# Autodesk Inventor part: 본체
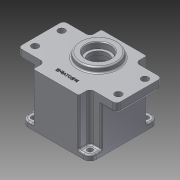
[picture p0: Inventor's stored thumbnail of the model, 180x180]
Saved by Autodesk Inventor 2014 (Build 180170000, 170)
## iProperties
Created: 2015-07
Part Number: 본체
Material: 알루미늄 6061
Document SubType Name: Modeling
Designer: Administrator
Density: 2.71 g/cm^3
Appearance: 알루미늄 - 평지
Mass: 704.944 g
Surface Area: 674.656 cm^2
Volume: 260.127 cm^3
Author: Administrator
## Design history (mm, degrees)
sketch "스케치1"
  geometry: L1 (-45, 45)-(45, 45); L2 (45, 45)-(45, -45); L3 (45, -45)-(-45, -45); L4 (-45, -45)-(-45, 45); L5 (-45, 45)-(45, -45); L6 (45, 45)-(-45, -45); 1 further point
  constraints: 12 end point, 2 midpoint, 2 parallel, 1 horizontal, 1 perpendicular
  dimensions: "d0" = 90 distance of L2.end L3.end; "d1" = 90 distance of L1.end L2.end
extrude "돌출1" new body sketch "스케치1" distance "d2" = 7; taper "d3" = 0 deg
sketch "스케치2"
  geometry: L1 (-30, 45)-(30, 45); L2 (30, 45)-(30, -45); L3 (30, -45)-(-30, -45); L4 (-30, -45)-(-30, 45); L5 (-30, 45)-(30, -45); L6 (30, 45)-(-30, -45); 3 further points
  constraints: 12 end point, 3 midpoint, 2 parallel, 1 coincident, 1 horizontal, 1 perpendicular
  dimensions: "d4" = 60 distance of L1.start L1.end; "d5" = 90 distance of L1.end L2.end
extrude "돌출2" join sketch "스케치2" distance "d6" = 63; taper "d7" = 0 deg
sketch "스케치3"
  geometry: L1 (-65, 30)-(65, 30); L2 (65, 30)-(65, -30); L3 (65, -30)-(-65, -30); L4 (-65, -30)-(-65, 30); L5 (-65, 30)-(65, -30); L6 (65, 30)-(-65, -30); 1 further point
  constraints: 12 end point, 2 midpoint, 2 parallel, 1 horizontal, 1 perpendicular
  dimensions: "d8" = 130 distance of L2.end L3.end; "d9" = 60 distance of L1.end L2.end
extrude "돌출3" join sketch "스케치3" distance "d10" = 12; taper "d11" = 0 deg
sketch "스케치4"
  geometry: L1 (-45, 30)-(45, 30); L2 (45, 30)-(45, -30); L3 (45, -30)-(-45, -30); L4 (-45, -30)-(-45, 30); L5 (-45, 30)-(45, -30); L6 (45, 30)-(-45, -30); 1 further point
  constraints: 12 end point, 2 midpoint, 2 parallel, 1 horizontal, 1 perpendicular
  dimensions: "d12" = 60 distance of L1.end L2.end; "d13" = 90 distance of L2.end L3.end
extrude "돌출4" join sketch "스케치4" distance "d14" = 63; taper "d15" = 0 deg
sketch "스케치5"
  geometry: C1 r 40 at (0, 0); 1 further point
  constraints: 1 centre point, 1 coincident
  dimensions: "d16" = 80 diameter of C1
extrude "돌출5" cut sketch "스케치5" distance "d17" = 9; taper "d18" = 0 deg
sketch "스케치6"
  geometry: C1 r 40 at (0, 0) reference; C2 r 39 at (0, 0)
  constraints: 1 centre point, 1 coincident
  dimensions: "d19" = 78 diameter of C2
extrude "돌출6" cut sketch "스케치6" distance "d20" = 52; taper "d21" = 0 deg
sketch "스케치7"
  geometry: C1 r 39 at (0, 0) reference; C2 r 20.5 at (0, 11); C3 r 14 at (0, -20)
  constraints: 2 centre point, 2 vertical alignment
  dimensions: "d22" = 11 distance of C1.centre C2.centre; "d23" = 20.5 radius of C2; "d24" = 28 diameter of C3; "d25" = 20 distance of C1.centre C3.centre
extrude "돌출7" join sketch "스케치7" distance "d26" = 7; taper "d27" = 0 deg
sketch "스케치8"
  geometry: C1 r 17.5 at (0, 11); A1 r 20.5 centre (0, 11) between (7.402, -8.117) and (-7.402, -8.117) reference; 1 further point
  constraints: 1 centre point, 1 coincident
  dimensions: "d30" = 35 diameter of C1
extrude "돌출8" cut sketch "스케치8" distance "d31" = 10; taper "d32" = 0 deg
sketch "스케치9"
  geometry: C1 r 11 at (0, -20); A1 r 14 centre (0, -20) between (-7.402, -8.117) and (7.402, -8.117) reference; 1 further point
  constraints: 1 centre point, 1 coincident
  dimensions: "d33" = 22 diameter of C1
extrude "돌출9" cut sketch "스케치9" distance "d34" = 7; taper "d35" = 0 deg
sketch "스케치10"
  geometry: C1 r 17.5 at (0, 0) reference; C2 r 12.5 at (0, 0); 1 further point
  constraints: 1 centre point, 1 coincident
  dimensions: "d36" = 25 diameter of C2
extrude "돌출10" cut sketch "스케치10" distance "d37" = 5; taper "d38" = 0 deg
sketch "스케치11"
  geometry: C1 r 11 at (0, 0) reference; C2 r 9.5 at (0, 0); 1 further point
  constraints: 1 centre point, 1 coincident
  dimensions: "d39" = 19 diameter of C2
extrude "돌출11" cut sketch "스케치11" distance "d40" = 1; taper "d41" = 0 deg
sketch "스케치12"
  geometry: C1 r 25 at (0, 11); 1 further point
  constraints: 1 centre point, 1 vertical alignment
  dimensions: "d42" = 50 diameter of C1; "d43" = 11 distance of point (0, 0) C1.centre
extrude "돌출12" join sketch "스케치12" distance "d44" = 7; taper "d45" = 0 deg
sketch "스케치13"
  geometry: C1 r 25 at (0, 0) reference; C2 r 16 at (0, 0); 1 further point
  constraints: 1 centre point, 1 coincident
  dimensions: "d46" = 32 diameter of C2
extrude "돌출13" cut sketch "스케치13" distance "d47" = 8; taper "d48" = 0 deg
sketch "스케치14"
  geometry: L1 (0, 0)-(39, 0); L2 (0, 0)-(24.749, 24.749); L3 (27.411, 21.763)-(30.401, 24.429); L4 (21.763, 27.411)-(24.429, 30.401); A1 r 39 centre (0, 0) between (39, 0) and (30.256, 24.608) reference; A2 r 35 centre (0, 0) between (24.749, 24.749) and (27.411, 21.763); A3 r 4 centre (24.749, 24.749) between (27.411, 21.763) and (21.763, 27.411); 1 further point
  constraints: 10 point on circle, 8 end point, 2 centre point, 2 coincident, 2 tangent, 1 horizontal
  dimensions: "d49" = 70 diameter of A2; "d50" = 45 deg angle of L1 L2; "d51" = 8 diameter of A3
extrude "돌출14" join sketch "스케치14" stored distance "d52" = 8; taper "d53" = 0 deg
sketch "스케치15"
  geometry: A1 r 4 centre (24.749, -24.749) between (27.411, -21.763) and (21.763, -27.411) reference; A2 r 4 centre (-24.749, -24.749) between (-21.763, -27.411) and (-27.411, -21.763) reference; A3 r 4 centre (-24.749, 24.749) between (-27.411, 21.763) and (-21.763, 27.411) reference; A4 r 4 centre (24.749, 24.749) between (21.763, 27.411) and (27.411, 21.763) reference; 4 further points
  constraints: 4 coincident
hole "구멍1" sketch "스케치15" at (-24.749, 24.749), (24.749, 24.749), (24.749, -24.749), (-24.749, -24.749) diameter "d57" = 3.459; stored, may be unused: countersink angle "d61" = 90 deg, drill point angle "d63" = 118 deg; dims "d58" = 12, "d59" = 4, "d60" = 2, "d62" = 15
fillet "모깎기1" dims "d64" = 8
sketch "스케치16"
  geometry: L1 (-45, 37)-(-45, 30) reference; L2 (-45, 30)-(-30, 30) reference; L3 (-30, 30)-(-30, 45) reference; L4 (-30, 45)-(-37, 45) reference; L5 (37, 45)-(30, 45) reference; L6 (30, 45)-(30, 30) reference; L7 (30, 30)-(45, 30) reference; L8 (45, 30)-(45, 37) reference; L9 (-37, -45)-(-30, -45) reference; L10 (-30, -45)-(-30, -30) reference; L11 (-30, -30)-(-45, -30) reference; L12 (-45, -30)-(-45, -37) reference; C1 r 3.5 at (37, -37); C2 r 3.5 at (37, 37); C3 r 3.5 at (-37, 37); C4 r 3.5 at (-37, -37); A1 r 8 centre (37, -37) between (37, -45) and (45, -37) reference; A2 r 8 centre (-37, 37) between (-37, 45) and (-45, 37) reference; A3 r 8 centre (37, 37) between (45, 37) and (37, 45) reference; A4 r 8 centre (-37, -37) between (-45, -37) and (-37, -45) reference; 1 further point
  constraints: 4 centre point, 4 coincident
  dimensions: "d65" = 7 diameter of C1; "d66" = 7 diameter of C2; "d67" = 7 diameter of C3; "d68" = 7 diameter of C4
extrude "돌출15" cut sketch "스케치16" stored distance "d69" = 8; taper "d70" = 0 deg
fillet "모깎기2" dims "d71" = 5
sketch "스케치17"
  geometry: C1 r 4.5 at (-55, 17.5); C2 r 4.5 at (-55, -17.5); C3 r 4.5 at (55, 17.5); C4 r 4.5 at (55, -17.5); 1 further point
  constraints: 4 centre point, 2 horizontal alignment, 2 vertical alignment
  dimensions: "d72" = 9 diameter of C1; "d73" = 9 diameter of C2; "d74" = 9 diameter of C4; "d75" = 9 diameter of C3; "d76" = 110 distance of C3.centre C1.centre; "d77" = 55 horizontal distance of point (0, 0) C1.centre; "d78" = 35 distance of C4.centre C3.centre; "d79" = 17.5 vertical distance of point (0, 0) C3.centre
extrude "돌출16" cut sketch "스케치17" stored distance "d80" = 8; taper "d81" = 0 deg
sketch "스케치18"
  geometry: L1 (-30, -45)-(30, -45) reference; 2 further points
  constraints: 1 vertical alignment, 1 other
  dimensions: "d82" = 15 distance from line of L1 point (0, -30)
feature "엠보싱1" sketch "스케치18" dims "d8" = 130, "d9" = 60, "d83" = 0.5, "d84" = 0
fillet "모깎기3" dims "d85" = 3.5
fillet "모깎기4" dims "d86" = 3
fillet "모깎기5" dims "d87" = 0.3
fillet "모깎기6" dims "d88" = 0.3
fillet "모깎기7" dims "d89" = 0.3
fillet "모깎기8" dims "d90" = 3
fillet "모깎기9" dims "d91" = 3
fillet "모깎기10" dims "d92" = 2
fillet "모깎기11" dims "d93" = 2
fillet "모깎기12" dims "d94" = 2
fillet "모깎기13" dims "d95" = 5
chamfer "모따기1" distance "d96" = 1; stored, may be unused: second distance "d97" = 2, angle "d98" = 45 deg
node "솔리드1"
pattern_circular "원형 패턴1" dims angle "d55" = 360 deg
node "투영된 루프1"
node "투영된 루프2"
node "투영된 루프3"
